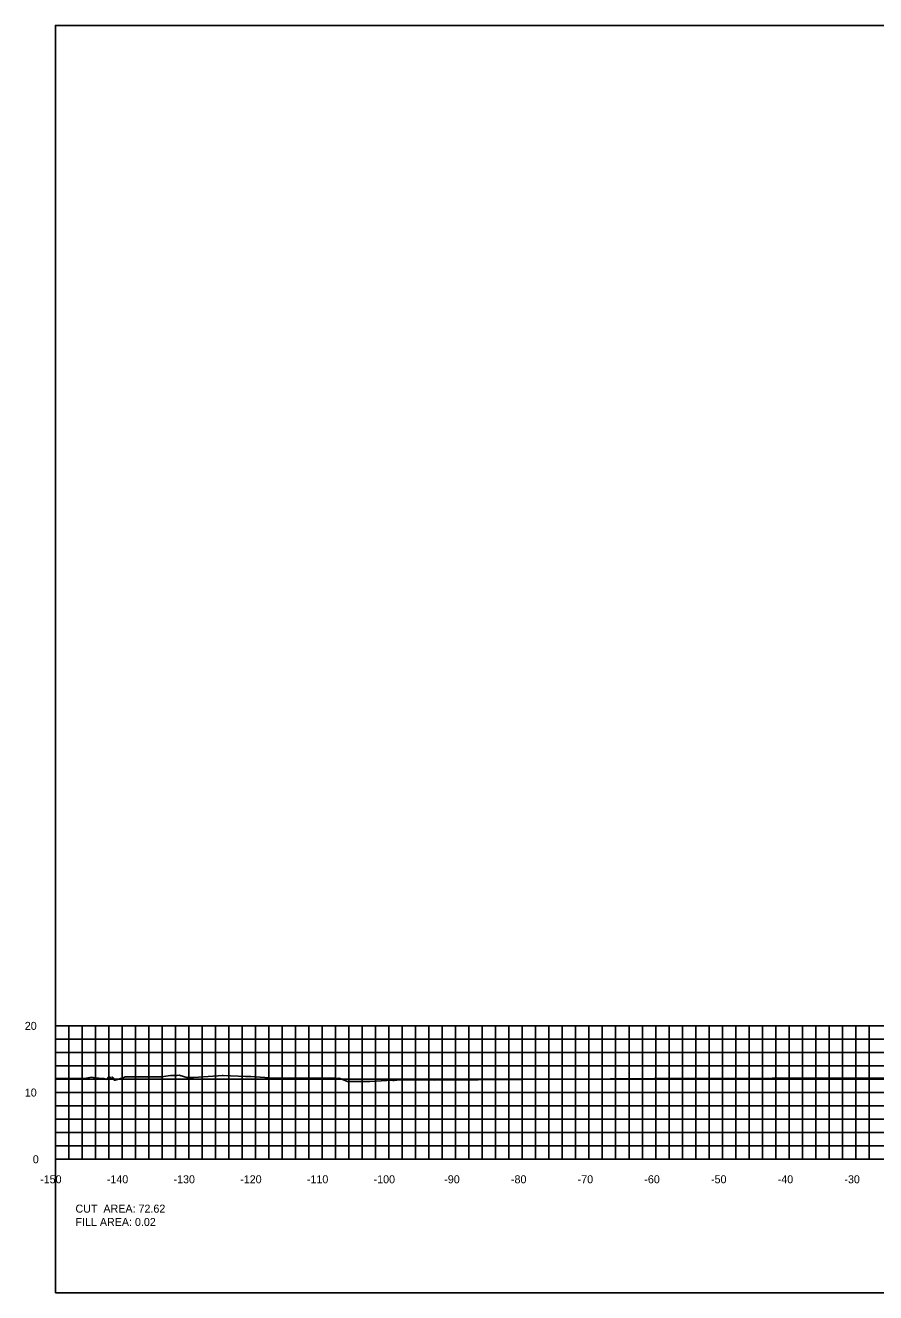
# Model space of a CAD drawing. Extents: x 1797759 to 1802785, y 249826 to 250371.
# Drawn here: x 1802476.5 to 1802604, y 250079.4 to 250269.4 of the extents above; entities that cross this region are included whole.
import ezdxf

# ---------------------------------------------------------------- set-up
doc = ezdxf.new("R2010")
doc.units = 0
for name, color, linetype in [('AXIS', 7, 'Continuous'), ('great seal', 7, 'Continuous'), ('Level 15', 7, 'Continuous'), ('Level 30', 7, 'Continuous'), ('Level 45', 7, 'Continuous'), ('Level 7', 7, 'Continuous'), ('LS-SURVEY POINT', 7, 'Continuous')]:
    doc.layers.add(name, color=color, linetype=linetype)

msp = doc.modelspace()

# ---------------------------------------------------------------- linework, layer by layer
at = {"layer": 'AXIS'}
msp.add_lwpolyline([(1802481, 250079.43), (1802781, 250079.43), (1802781, 250269.43), (1802481, 250269.43)], close=True, dxfattribs=at)
at = {"layer": 'great seal'}
msp.add_lwpolyline([(1802481, 250111.54), (1802484.55, 250111.53), (1802485.61, 250111.61), (1802485.61, 250111.61), (1802486.45, 250111.74), (1802487.2, 250111.58), (1802487.24, 250111.6), (1802487.25, 250111.61), (1802487.26, 250111.6), (1802487.27, 250111.6), (1802487.35, 250111.58), (1802487.44, 250111.57), (1802487.53, 250111.55), (1802487.59, 250111.53), (1802487.63, 250111.53), (1802487.7, 250111.52), (1802487.74, 250111.52), (1802487.86, 250111.52), (1802488, 250111.52), (1802488.15, 250111.53), (1802488.25, 250111.53), (1802488.34, 250111.5), (1802488.44, 250111.47), (1802488.54, 250111.41), (1802488.72, 250111.43), (1802488.95, 250111.72), (1802488.95, 250111.7), (1802488.95, 250111.72), (1802489.22, 250111.73), (1802489.23, 250111.54), (1802489.3, 250111.5), (1802489.33, 250111.49), (1802489.46, 250111.54), (1802489.48, 250111.78), (1802489.55, 250111.73), (1802489.66, 250111.66), (1802489.84, 250111.28), (1802489.94, 250111.31), (1802491.12, 250111.66), (1802491.37, 250111.76), (1802491.37, 250111.76), (1802491.42, 250111.78), (1802491.43, 250111.77), (1802491.44, 250111.78), (1802491.45, 250111.78), (1802491.47, 250111.78), (1802491.48, 250111.78), (1802491.48, 250111.78), (1802491.5, 250111.78), (1802491.5, 250111.78), (1802491.5, 250111.78), (1802491.52, 250111.78), (1802496.9, 250111.8), (1802497.92, 250111.94), (1802498.24, 250111.97), (1802499.27, 250112.01), (1802499.56, 250112.02), (1802499.7, 250111.99), (1802500.68, 250111.69), (1802501.71, 250111.68), (1802504.63, 250111.9), (1802505.38, 250111.95), (1802505.98, 250111.97), (1802506.15, 250111.97), (1802509.51, 250111.86), (1802510.29, 250111.85), (1802513.79, 250111.61), (1802520.37, 250111.57), (1802522.14, 250111.58), (1802523.04, 250111.58), (1802523.46, 250111.55), (1802523.53, 250111.58), (1802523.96, 250111.44), (1802524.05, 250111.39), (1802524.79, 250111.09), (1802525.45, 250111.1), (1802525.68, 250111.09), (1802525.76, 250111.07), (1802526.07, 250111.07), (1802526.76, 250111.07), (1802526.87, 250111.09), (1802528.15, 250111.08), (1802531.54, 250111.27), (1802531.57, 250111.24), (1802531.78, 250111.24), (1802532.21, 250111.29), (1802536.69, 250111.33), (1802536.71, 250111.33), (1802537.77, 250111.31), (1802570.76, 250111.56), (1802588.48, 250111.61), (1802612.48, 250111.6)], dxfattribs=at)
at = {"layer": 'Level 15'}
for p, q in [((1802481, 250119.43), (1802781, 250119.43)), ((1802481, 250099.43), (1802481, 250119.43)), ((1802483, 250099.43), (1802483, 250119.43)), ((1802485, 250099.43), (1802485, 250119.43)), ((1802487, 250099.43), (1802487, 250119.43)), ((1802489, 250099.43), (1802489, 250119.43)), ((1802491, 250099.43), (1802491, 250119.43)), ((1802493, 250099.43), (1802493, 250119.43)), ((1802495, 250099.43), (1802495, 250119.43)), ((1802497, 250099.43), (1802497, 250119.43)), ((1802499, 250099.43), (1802499, 250119.43)), ((1802501, 250099.43), (1802501, 250119.43)), ((1802503, 250099.43), (1802503, 250119.43)), ((1802505, 250099.43), (1802505, 250119.43)), ((1802507, 250099.43), (1802507, 250119.43)), ((1802509, 250099.43), (1802509, 250119.43)), ((1802511, 250099.43), (1802511, 250119.43)), ((1802513, 250099.43), (1802513, 250119.43)), ((1802515, 250099.43), (1802515, 250119.43)), ((1802517, 250099.43), (1802517, 250119.43)), ((1802519, 250099.43), (1802519, 250119.43)), ((1802521, 250099.43), (1802521, 250119.43)), ((1802523, 250099.43), (1802523, 250119.43)), ((1802525, 250099.43), (1802525, 250119.43)), ((1802527, 250099.43), (1802527, 250119.43)), ((1802529, 250099.43), (1802529, 250119.43)), ((1802531, 250099.43), (1802531, 250119.43)), ((1802533, 250099.43), (1802533, 250119.43)), ((1802535, 250099.43), (1802535, 250119.43)), ((1802537, 250099.43), (1802537, 250119.43)), ((1802539, 250099.43), (1802539, 250119.43)), ((1802541, 250099.43), (1802541, 250119.43)), ((1802543, 250099.43), (1802543, 250119.43)), ((1802545, 250099.43), (1802545, 250119.43)), ((1802547, 250099.43), (1802547, 250119.43)), ((1802549, 250099.43), (1802549, 250119.43)), ((1802551, 250099.43), (1802551, 250119.43)), ((1802553, 250099.43), (1802553, 250119.43)), ((1802555, 250099.43), (1802555, 250119.43)), ((1802557, 250099.43), (1802557, 250119.43)), ((1802559, 250099.43), (1802559, 250119.43)), ((1802561, 250099.43), (1802561, 250119.43)), ((1802563, 250099.43), (1802563, 250119.43)), ((1802565, 250099.43), (1802565, 250119.43)), ((1802567, 250099.43), (1802567, 250119.43)), ((1802569, 250099.43), (1802569, 250119.43)), ((1802571, 250099.43), (1802571, 250119.43)), ((1802573, 250099.43), (1802573, 250119.43)), ((1802575, 250099.43), (1802575, 250119.43)), ((1802577, 250099.43), (1802577, 250119.43)), ((1802579, 250099.43), (1802579, 250119.43)), ((1802581, 250099.43), (1802581, 250119.43)), ((1802583, 250099.43), (1802583, 250119.43)), ((1802585, 250099.43), (1802585, 250119.43)), ((1802587, 250099.43), (1802587, 250119.43)), ((1802589, 250099.43), (1802589, 250119.43)), ((1802591, 250099.43), (1802591, 250119.43)), ((1802593, 250099.43), (1802593, 250119.43)), ((1802595, 250099.43), (1802595, 250119.43)), ((1802597, 250099.43), (1802597, 250119.43)), ((1802599, 250099.43), (1802599, 250119.43)), ((1802601, 250099.43), (1802601, 250119.43)), ((1802603, 250099.43), (1802603, 250119.43)), ((1802481, 250117.43), (1802781, 250117.43)), ((1802481, 250115.43), (1802781, 250115.43)), ((1802481, 250113.43), (1802781, 250113.43)), ((1802481, 250111.43), (1802781, 250111.43)), ((1802481, 250109.43), (1802781, 250109.43)), ((1802481, 250107.43), (1802781, 250107.43)), ((1802481, 250105.43), (1802781, 250105.43)), ((1802481, 250103.43), (1802781, 250103.43)), ((1802481, 250101.43), (1802781, 250101.43)), ((1802481, 250099.43), (1802781, 250099.43))]:
    msp.add_line(p, q, dxfattribs=at)
at = {"layer": 'Level 30'}
for p, q in [((1802480.94, 250119.43), (1802481, 250119.43)), ((1802481, 250099.43), (1802481, 250119.43)), ((1802480.94, 250109.43), (1802481, 250109.43)), ((1802480.94, 250099.43), (1802481, 250099.43)), ((1802481, 250099.43), (1802781, 250099.43)), ((1802481, 250099.37), (1802481, 250099.43)), ((1802491, 250099.37), (1802491, 250099.43)), ((1802501, 250099.37), (1802501, 250099.43)), ((1802511, 250099.37), (1802511, 250099.43)), ((1802521, 250099.37), (1802521, 250099.43)), ((1802531, 250099.37), (1802531, 250099.43)), ((1802541, 250099.37), (1802541, 250099.43)), ((1802551, 250099.37), (1802551, 250099.43)), ((1802561, 250099.37), (1802561, 250099.43)), ((1802571, 250099.37), (1802571, 250099.43)), ((1802581, 250099.37), (1802581, 250099.43)), ((1802591, 250099.37), (1802591, 250099.43)), ((1802601, 250099.37), (1802601, 250099.43))]:
    msp.add_line(p, q, dxfattribs=at)

# ---------------------------------------------------------------- texts
msp.add_text('-', height=0.0001, dxfattribs=at).set_placement((1802481, 250099.43))
at = {"layer": 'Level 45'}
for s, p in [('-150', (1802478.7, 250095.83)), ('-140', (1802488.7, 250095.83)), ('-130', (1802498.7, 250095.83)), ('-120', (1802508.7, 250095.83)), ('-110', (1802518.7, 250095.83)), ('-100', (1802528.7, 250095.83)), ('-90', (1802539.3, 250095.83)), ('-80', (1802549.3, 250095.83)), ('-70', (1802559.3, 250095.83)), ('-60', (1802569.3, 250095.83)), ('-50', (1802579.3, 250095.83)), ('-40', (1802589.3, 250095.83)), ('-30', (1802599.3, 250095.83))]:
    msp.add_text(s, height=1.2, dxfattribs=at).set_placement(p)
at = {"layer": 'Level 7'}
for s, p in [('20', (1802476.4, 250118.83)), ('10', (1802476.4, 250108.83)), ('0', (1802477.6, 250098.83))]:
    msp.add_text(s, height=1.2, dxfattribs=at).set_placement(p)
at = {"layer": 'LS-SURVEY POINT'}
for s, p in [('CUT  AREA: 72.62', (1802484, 250091.43)), ('FILL AREA: 0.02', (1802484, 250089.43))]:
    msp.add_text(s, height=1.2, dxfattribs=at).set_placement(p)

doc.saveas('drawing.dxf')
